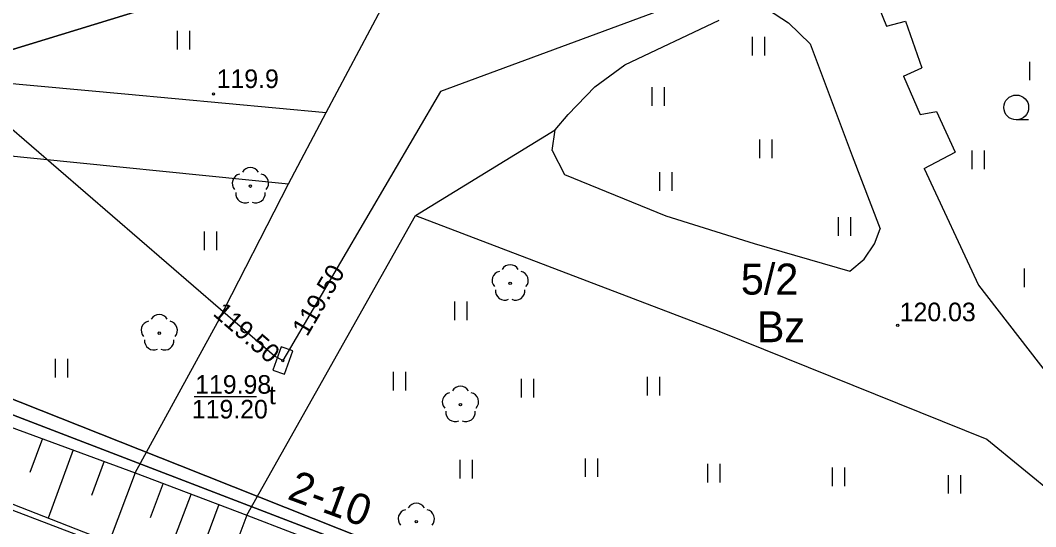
# Model space of a CAD drawing. Extents: x 6432121 to 6432331, y 5662538 to 5662686.
# Drawn here: x 6432202.58 to 6432243.57, y 5662603.09 to 5662623.53 of the extents above; entities that cross this region are included whole.
import ezdxf

# ---------------------------------------------------------------- set-up
doc = ezdxf.new("R2010")
doc.units = 0
for name, color, linetype in [('Warstwa 1', 7, 'Continuous'), ('Warstwa 10', 7, 'Continuous'), ('Warstwa 11', 7, 'Continuous'), ('Warstwa 12', 7, 'Continuous'), ('Warstwa 13', 7, 'Continuous'), ('Warstwa 14', 7, 'Continuous'), ('Warstwa 15', 7, 'Continuous'), ('Warstwa 2', 7, 'Continuous'), ('Warstwa 20', 7, 'Continuous'), ('Warstwa 21', 7, 'Continuous'), ('Warstwa 25', 7, 'Continuous'), ('Warstwa 4', 7, 'Continuous'), ('Warstwa 5', 7, 'Continuous'), ('Warstwa 6', 7, 'Continuous'), ('Warstwa 9', 7, 'Continuous')]:
    doc.layers.add(name, color=color, linetype=linetype)

msp = doc.modelspace()

# ---------------------------------------------------------------- linework, layer by layer
at = {"layer": 'Warstwa 1'}
for p, q in [((6432193.86, 5662619.79), (6432228.29, 5662630.34)), ((6432193.86, 5662619.79), (6432228.29, 5662630.34)), ((6432180.9, 5662615.82), (6432259.074, 5662585.787)), ((6432180.9, 5662615.82), (6432259.074, 5662585.787))]:
    msp.add_line(p, q, dxfattribs=at)
at = {"layer": 'Warstwa 10'}
for p, q in [((6432167.648, 5662617.501), (6432210.732, 5662600.706)), ((6432199.73, 5662608.02), (6432207.218, 5662605.272)), ((6432203.475, 5662606.646), (6432202.974, 5662605.285)), ((6432204.722, 5662606.188), (6432203.714, 5662603.441)), ((6432205.97, 5662605.73), (6432205.458, 5662604.345)), ((6432207.218, 5662605.272), (6432206.177, 5662602.481)), ((6432207.218, 5662605.272), (6432211.732, 5662603.561)), ((6432208.347, 5662604.844), (6432207.82, 5662603.445)), ((6432209.475, 5662604.416), (6432208.412, 5662601.611)), ((6432210.603, 5662603.989), (6432210.068, 5662602.581)), ((6432211.732, 5662603.561), (6432210.651, 5662600.738)), ((6432211.732, 5662603.561), (6432241.32, 5662592.163))]:
    msp.add_line(p, q, dxfattribs=at)
at = {"layer": 'Warstwa 11'}
for centre in [(6432211.872, 5662616.841), (6432222.36, 5662612.916), (6432208.193, 5662610.904), (6432220.351, 5662608.017), (6432218.57, 5662603.292)]:
    msp.add_circle(centre, 0.05, dxfattribs=at)
for centre, start, end in [((6432211.872, 5662617.216), 30.1471, 149.8529), ((6432211.515, 5662616.957), 102.1471, 221.8529), ((6432212.229, 5662616.957), 318.1471, 77.8529), ((6432211.652, 5662616.538), 174.1471, 293.8529), ((6432212.092, 5662616.538), 246.1471, 5.8529), ((6432222.003, 5662613.032), 102.1471, 221.8529), ((6432222.36, 5662613.291), 30.1471, 149.8529), ((6432222.717, 5662613.032), 318.1471, 77.8529), ((6432222.14, 5662612.613), 174.1471, 293.8529), ((6432222.58, 5662612.613), 246.1471, 5.8529), ((6432207.836, 5662611.02), 102.1471, 221.8529), ((6432208.193, 5662611.279), 30.1471, 149.8529), ((6432208.55, 5662611.02), 318.1471, 77.8529), ((6432207.973, 5662610.601), 174.1471, 293.8529), ((6432208.413, 5662610.601), 246.1471, 5.8529), ((6432219.994, 5662608.133), 102.1471, 221.8529), ((6432220.351, 5662608.392), 30.1471, 149.8529), ((6432220.708, 5662608.133), 318.1471, 77.8529), ((6432220.131, 5662607.714), 174.1471, 293.8529), ((6432220.571, 5662607.714), 246.1471, 5.8529), ((6432218.57, 5662603.667), 30.1471, 149.8529), ((6432218.213, 5662603.408), 102.1471, 221.8529), ((6432218.927, 5662603.408), 318.1471, 77.8529)]:
    msp.add_arc(centre, 0.375, start, end, dxfattribs=at)
at = {"layer": 'Warstwa 12'}
for points in [[(6432248.82, 5662629.93), (6432248.54, 5662629.72), (6432247.48, 5662630.2), (6432247.186, 5662630.33), (6432247.012, 5662630.407), (6432246.73, 5662630.84), (6432246.374, 5662630.582), (6432219.55, 5662620.66), (6432213.49, 5662610.33), (6432213.18, 5662609.798), (6432212.84, 5662609.97), (6432201.94, 5662619.39), (6432188.48, 5662659.63), (6432188.372, 5662660.264), (6432188.26, 5662660.96), (6432187.54, 5662663.58), (6432189.456, 5662664.144), (6432190.073, 5662664.038), (6432190.591, 5662664.478), (6432199.77, 5662667.18), (6432202.78, 5662668.86), (6432236.07, 5662677.73), (6432238.751, 5662681.053)], [(6432151.934, 5662659.962), (6432163.647, 5662662.364), (6432165.031, 5662661.271), (6432166.026, 5662656.887), (6432167.998, 5662648.227), (6432170.198, 5662638.637), (6432172.215, 5662629.789), (6432174.2, 5662621.336), (6432174.764, 5662618.709), (6432176.004, 5662617.499), (6432181.388, 5662615.664), (6432187.493, 5662613.63), (6432194.563, 5662611.29), (6432209.024, 5662605.561), (6432218.668, 5662601.72), (6432230.17, 5662597.186), (6432236.4, 5662594.702), (6432238.551, 5662593.742), (6432242.89, 5662591.993), (6432244.915, 5662591.158), (6432249.823, 5662589.199), (6432255.518, 5662586.99), (6432264.175, 5662583.483)], [(6432156.818, 5662630.202), (6432158.039, 5662625.384), (6432159.105, 5662620.911), (6432168.554, 5662616.714), (6432182.01, 5662611.519), (6432201.034, 5662604.23), (6432217.284, 5662598.028), (6432236.124, 5662590.737), (6432242.639, 5662588.267), (6432252.12, 5662584.559), (6432258.988, 5662581.806), (6432263.17, 5662580.184), (6432269.496, 5662577.686)], [(6432244.915, 5662591.158), (6432242.89, 5662591.993), (6432238.551, 5662593.742), (6432237.475, 5662594.222), (6432236.4, 5662594.702), (6432230.17, 5662597.186), (6432224.419, 5662599.453), (6432218.668, 5662601.72), (6432209.024, 5662605.561), (6432194.563, 5662611.29), (6432187.493, 5662613.63), (6432176.004, 5662617.499), (6432174.764, 5662618.709), (6432174.2, 5662621.336), (6432172.215, 5662629.789)]]:
    msp.add_lwpolyline(points, dxfattribs=at)
at = {"layer": 'Warstwa 13'}
msp.add_circle((6432210.384, 5662620.56), 0.045, dxfattribs=at)
at = {"layer": 'Warstwa 14'}
msp.add_line((6432212.123, 5662608.336), (6432209.608, 5662608.336), dxfattribs=at)
msp.add_circle((6432213.18, 5662609.798), 0.045, dxfattribs=at)
msp.add_circle((6432213.18, 5662609.798), 0.045, dxfattribs=at)
msp.add_circle((6432213.18, 5662609.798), 0.045, dxfattribs=at)
msp.add_circle((6432213.18, 5662609.798), 0.045, dxfattribs=at)
at = {"layer": 'Warstwa 20'}
for p, q in [((6432199.73, 5662608.02), (6432207.218, 5662605.272)), ((6432207.218, 5662605.272), (6432211.732, 5662603.561)), ((6432211.732, 5662603.561), (6432241.32, 5662592.163))]:
    msp.add_line(p, q, dxfattribs=at)
at = {"layer": 'Warstwa 21'}
msp.add_line((6432167.648, 5662617.501), (6432210.732, 5662600.706), dxfattribs=at)
at = {"layer": 'Warstwa 25'}
msp.add_circle((6432238.002, 5662611.224), 0.045, dxfattribs=at)
at = {"layer": 'Warstwa 4'}
msp.add_lwpolyline([(6432213.248, 5662609.243), (6432213.583, 5662610.185), (6432213.112, 5662610.353), (6432212.777, 5662609.411)], close=True, dxfattribs=at)
at = {"layer": 'Warstwa 5'}
for p, q in [((6432235.929, 5662627.325), (6432237.553, 5662623.292)), ((6432214.929, 5662619.809), (6432217.146, 5662623.978)), ((6432232.749, 5662623.985), (6432233.599, 5662623.428)), ((6432226.984, 5662621.736), (6432230.799, 5662623.54)), ((6432233.599, 5662623.428), (6432234.463, 5662622.58)), ((6432237.553, 5662623.292), (6432238.313, 5662623.496)), ((6432238.313, 5662623.496), (6432238.979, 5662621.614)), ((6432208.923, 5662622.353), (6432208.923, 5662623.103)), ((6432209.423, 5662622.353), (6432209.423, 5662623.103)), ((6432232.142, 5662622.112), (6432232.142, 5662622.862)), ((6432232.642, 5662622.112), (6432232.642, 5662622.862)), ((6432234.463, 5662622.58), (6432236.16, 5662618.057)), ((6432225.777, 5662620.844), (6432226.984, 5662621.736)), ((6432238.233, 5662621.274), (6432238.979, 5662621.614)), ((6432243.334, 5662621.112), (6432243.334, 5662621.862)), ((6432238.233, 5662621.274), (6432238.911, 5662619.734)), ((6432200.367, 5662621.152), (6432206.803, 5662620.569)), ((6432224.694, 5662619.726), (6432225.777, 5662620.844)), ((6432228.093, 5662620.078), (6432228.093, 5662620.828)), ((6432228.593, 5662620.078), (6432228.593, 5662620.828)), ((6432206.803, 5662620.569), (6432214.929, 5662619.809)), ((6432187.151, 5662619.575), (6432213.408, 5662616.935)), ((6432224.181, 5662619.109), (6432224.694, 5662619.726)), ((6432238.911, 5662619.734), (6432239.563, 5662619.847)), ((6432239.563, 5662619.847), (6432240.324, 5662618.206)), ((6432224.054, 5662618.273), (6432224.181, 5662619.109)), ((6432232.435, 5662617.974), (6432232.435, 5662618.724)), ((6432232.935, 5662617.974), (6432232.935, 5662618.724)), ((6432224.054, 5662618.273), (6432224.548, 5662617.312)), ((6432236.16, 5662618.057), (6432237.3, 5662615.111)), ((6432239.074, 5662617.554), (6432240.324, 5662618.206)), ((6432241.003, 5662617.531), (6432241.003, 5662618.281)), ((6432241.503, 5662617.531), (6432241.503, 5662618.281)), ((6432239.074, 5662617.554), (6432241.266, 5662612.847)), ((6432224.548, 5662617.312), (6432228.642, 5662615.634)), ((6432228.403, 5662616.65), (6432228.403, 5662617.4)), ((6432228.903, 5662616.65), (6432228.903, 5662617.4)), ((6432210.544, 5662611.33), (6432213.408, 5662616.935)), ((6432211.732, 5662603.561), (6432218.536, 5662615.659)), ((6432218.536, 5662615.659), (6432230.776, 5662610.984)), ((6432228.642, 5662615.634), (6432232.207, 5662614.52)), ((6432235.616, 5662614.83), (6432235.616, 5662615.58)), ((6432236.116, 5662614.83), (6432236.116, 5662615.58)), ((6432237.06, 5662614.509), (6432237.3, 5662615.111)), ((6432210.013, 5662614.253), (6432210.013, 5662615.003)), ((6432210.513, 5662614.253), (6432210.513, 5662615.003)), ((6432232.207, 5662614.52), (6432236.065, 5662613.401)), ((6432236.644, 5662613.891), (6432237.06, 5662614.509)), ((6432236.065, 5662613.401), (6432236.644, 5662613.891)), ((6432243.122, 5662612.761), (6432243.122, 5662613.511)), ((6432241.266, 5662612.847), (6432247.012, 5662605.394)), ((6432220.128, 5662611.433), (6432220.128, 5662612.183)), ((6432220.628, 5662611.433), (6432220.628, 5662612.183)), ((6432207.218, 5662605.272), (6432210.544, 5662611.33)), ((6432230.776, 5662610.984), (6432241.597, 5662606.63)), ((6432204.003, 5662609.112), (6432204.003, 5662609.862)), ((6432204.503, 5662609.112), (6432204.503, 5662609.862)), ((6432217.653, 5662608.596), (6432217.653, 5662609.346)), ((6432218.153, 5662608.596), (6432218.153, 5662609.346)), ((6432222.818, 5662608.306), (6432222.818, 5662609.056)), ((6432223.318, 5662608.306), (6432223.318, 5662609.056)), ((6432227.898, 5662608.39), (6432227.898, 5662609.14)), ((6432228.398, 5662608.39), (6432228.398, 5662609.14)), ((6432199.73, 5662608.02), (6432207.218, 5662605.272)), ((6432241.597, 5662606.63), (6432244.431, 5662604.308)), ((6432220.337, 5662605.037), (6432220.337, 5662605.787)), ((6432220.837, 5662605.037), (6432220.837, 5662605.787)), ((6432225.395, 5662605.1), (6432225.395, 5662605.85)), ((6432225.895, 5662605.1), (6432225.895, 5662605.85)), ((6432230.341, 5662604.875), (6432230.341, 5662605.625)), ((6432230.841, 5662604.875), (6432230.841, 5662605.625)), ((6432235.374, 5662604.731), (6432235.374, 5662605.481)), ((6432235.874, 5662604.731), (6432235.874, 5662605.481)), ((6432240.055, 5662604.427), (6432240.055, 5662605.177)), ((6432240.555, 5662604.427), (6432240.555, 5662605.177)), ((6432211.732, 5662603.561), (6432241.32, 5662592.163))]:
    msp.add_line(p, q, dxfattribs=at)
at = {"layer": 'Warstwa 6'}
msp.add_line((6432243.289, 5662619.516), (6432242.789, 5662619.516), dxfattribs=at)
for points in [[(6432166.394, 5662623.975), (6432164.332, 5662622.19), (6432180.9, 5662615.82), (6432193.86, 5662619.79), (6432228.29, 5662630.34), (6432246.69, 5662636.13), (6432245.39, 5662639.916), (6432234.842, 5662644.244)], [(6432259.074, 5662585.787), (6432263.163, 5662588.197), (6432246.69, 5662636.13), (6432228.29, 5662630.34), (6432193.86, 5662619.79), (6432180.9, 5662615.82)], [(6432180.9, 5662615.82), (6432147.05, 5662605.45), (6432141.907, 5662600.47), (6432155.186, 5662604.45), (6432246.621, 5662569.177), (6432269.007, 5662560.534), (6432263.163, 5662588.197), (6432259.074, 5662585.787)]]:
    msp.add_lwpolyline(points, close=True, dxfattribs=at)
msp.add_circle((6432242.789, 5662620.016), 0.5, dxfattribs=at)
at = {"layer": 'Warstwa 9'}
for p, q in [((6432235.929, 5662627.325), (6432237.553, 5662623.292)), ((6432214.929, 5662619.809), (6432217.146, 5662623.978)), ((6432232.749, 5662623.985), (6432233.599, 5662623.428)), ((6432226.984, 5662621.736), (6432230.799, 5662623.54)), ((6432233.599, 5662623.428), (6432234.463, 5662622.58)), ((6432237.553, 5662623.292), (6432238.313, 5662623.496)), ((6432238.313, 5662623.496), (6432238.979, 5662621.614)), ((6432234.463, 5662622.58), (6432236.16, 5662618.057)), ((6432225.777, 5662620.844), (6432226.984, 5662621.736)), ((6432238.233, 5662621.274), (6432238.979, 5662621.614)), ((6432238.233, 5662621.274), (6432238.911, 5662619.734)), ((6432200.367, 5662621.152), (6432206.803, 5662620.569)), ((6432224.694, 5662619.726), (6432225.777, 5662620.844)), ((6432206.803, 5662620.569), (6432214.929, 5662619.809)), ((6432187.151, 5662619.575), (6432213.408, 5662616.935)), ((6432213.408, 5662616.935), (6432214.929, 5662619.809)), ((6432213.408, 5662616.935), (6432214.929, 5662619.809)), ((6432224.181, 5662619.109), (6432224.694, 5662619.726)), ((6432238.911, 5662619.734), (6432239.563, 5662619.847)), ((6432239.563, 5662619.847), (6432240.324, 5662618.206)), ((6432218.536, 5662615.659), (6432224.181, 5662619.109)), ((6432218.536, 5662615.659), (6432224.181, 5662619.109)), ((6432224.054, 5662618.273), (6432224.181, 5662619.109)), ((6432224.054, 5662618.273), (6432224.548, 5662617.312)), ((6432236.16, 5662618.057), (6432237.3, 5662615.111)), ((6432239.074, 5662617.554), (6432240.324, 5662618.206)), ((6432239.074, 5662617.554), (6432241.266, 5662612.847)), ((6432224.548, 5662617.312), (6432228.642, 5662615.634)), ((6432210.544, 5662611.33), (6432213.408, 5662616.935)), ((6432211.732, 5662603.561), (6432218.536, 5662615.659)), ((6432218.536, 5662615.659), (6432230.776, 5662610.984)), ((6432228.642, 5662615.634), (6432232.207, 5662614.52)), ((6432237.06, 5662614.509), (6432237.3, 5662615.111)), ((6432232.207, 5662614.52), (6432236.065, 5662613.401)), ((6432236.644, 5662613.891), (6432237.06, 5662614.509)), ((6432236.065, 5662613.401), (6432236.644, 5662613.891)), ((6432241.266, 5662612.847), (6432247.012, 5662605.394)), ((6432207.218, 5662605.272), (6432210.544, 5662611.33)), ((6432230.776, 5662610.984), (6432241.597, 5662606.63)), ((6432189.19, 5662609.104), (6432210.732, 5662600.706)), ((6432241.597, 5662606.63), (6432244.431, 5662604.308)), ((6432207.218, 5662605.272), (6432211.732, 5662603.561))]:
    msp.add_line(p, q, dxfattribs=at)

# ---------------------------------------------------------------- texts
at = {"layer": 'Warstwa 13'}
msp.add_text('119.9', height=0.75, dxfattribs=at).set_placement((6432210.509, 5662620.8))
at = {"layer": 'Warstwa 14'}
for s, height, rotation, p in [('119.50', 0.75, 59.6048, (6432214.162, 5662610.733)), ('119.50', 0.75, 319.1661, (6432210.324, 5662611.649)), ('2-10', 1.25, 339.678, (6432213.318, 5662604.226))]:
    msp.add_text(s, height=height, rotation=rotation, dxfattribs=at).set_placement(p)
msp.add_text('119.20', height=0.75, dxfattribs=at).set_placement((6432209.508, 5662607.46))
at = {"layer": 'Warstwa 15'}
for s, height, p in [('5/2', 1.25, (6432231.67, 5662612.462)), ('119.98', 0.75, (6432209.643, 5662608.46))]:
    msp.add_text(s, height=height, dxfattribs=at).set_placement(p)
at = {"layer": 'Warstwa 2'}
msp.add_text('Bz', height=1.25, dxfattribs=at).set_placement((6432232.315, 5662610.538))
at = {"layer": 'Warstwa 25'}
msp.add_text('120.03', height=0.75, dxfattribs=at).set_placement((6432238.085, 5662611.386))
at = {"layer": 'Warstwa 5'}
msp.add_text('t', height=0.75, dxfattribs=at).set_placement((6432212.614, 5662608.034))

doc.saveas('drawing.dxf')
